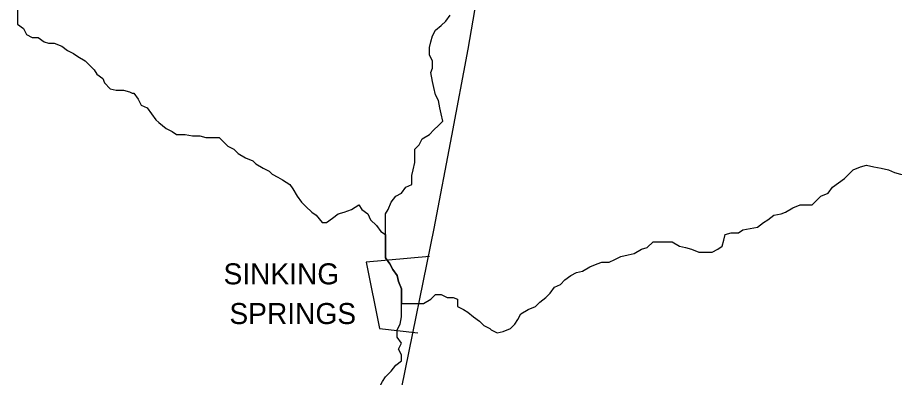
# Model space of a CAD drawing. Extents: x 0 to 40.2, y 0 to 22.
# Drawn here: x 4.306 to 5.119, y 17.878 to 18.212 of the extents above; entities that cross this region are included whole.
import ezdxf

# ---------------------------------------------------------------- set-up
doc = ezdxf.new("R2010")
doc.units = 0
doc.layers.add('Default', color=7, linetype='Continuous')

msp = doc.modelspace()

# ---------------------------------------------------------------- linework, layer by layer
at = {"layer": 'Default'}
for points in [[(4.7818, 18.51094), (4.75726, 18.37868), (4.73681, 18.26143), (4.72318, 18.18235), (4.70818, 18.10191), (4.69182, 18.01601), (4.66182, 17.86877)], [(4.31551, 18.30915), (4.31551, 18.30233), (4.31551, 18.29552), (4.31415, 18.29006), (4.31415, 18.28325), (4.31279, 18.27643), (4.31279, 18.26961), (4.31142, 18.26279), (4.31142, 18.25734), (4.31142, 18.25052), (4.3087, 18.24507), (4.3087, 18.23689), (4.3087, 18.23144), (4.30733, 18.22462), (4.30597, 18.2178), (4.30597, 18.21235), (4.30597, 18.20553), (4.30597, 18.20553)], [(4.64682, 18.01056), (4.64682, 18.01601), (4.64682, 18.02147), (4.64682, 18.02965), (4.64955, 18.03374), (4.65228, 18.04056), (4.65637, 18.04601), (4.66182, 18.04874), (4.66591, 18.05419), (4.67137, 18.05692), (4.67137, 18.0651), (4.67273, 18.07055), (4.67409, 18.07737), (4.67409, 18.08282), (4.67409, 18.08964), (4.67818, 18.09373), (4.68091, 18.09918), (4.68773, 18.10327), (4.69182, 18.10736), (4.69591, 18.11145), (4.7, 18.11554), (4.69863, 18.12236), (4.69727, 18.12782), (4.69591, 18.13463), (4.69318, 18.14009), (4.69182, 18.1469), (4.69045, 18.15236), (4.68909, 18.16054), (4.69045, 18.16463), (4.69045, 18.17144), (4.68773, 18.1769), (4.68773, 18.18372), (4.68909, 18.18917), (4.69045, 18.19462), (4.69318, 18.20008), (4.69863, 18.20417), (4.70272, 18.20826), (4.70681, 18.21371)], [(4.30597, 18.20553), (4.31142, 18.20144), (4.31415, 18.19599), (4.3196, 18.19326), (4.32506, 18.19326), (4.33051, 18.18917), (4.3346, 18.18781), (4.34005, 18.18781), (4.34687, 18.18508), (4.35233, 18.18099), (4.35778, 18.17826), (4.36187, 18.17554), (4.36869, 18.17144), (4.37141, 18.16872), (4.37687, 18.16326), (4.37959, 18.15917), (4.38505, 18.15508), (4.38641, 18.15099), (4.39186, 18.14554), (4.39732, 18.14418), (4.40414, 18.14418), (4.40959, 18.14281), (4.41232, 18.14145), (4.41368, 18.14145)], [(4.41368, 18.14145), (4.41777, 18.136), (4.4205, 18.13054), (4.42595, 18.12782), (4.43004, 18.12236), (4.43413, 18.11691), (4.43686, 18.11418), (4.44367, 18.10873), (4.44913, 18.106), (4.45322, 18.10327), (4.4614, 18.10327), (4.46822, 18.10191), (4.47503, 18.10191), (4.48049, 18.10055), (4.48594, 18.10055), (4.49276, 18.10055), (4.49685, 18.09646), (4.50094, 18.09237), (4.50639, 18.08964), (4.51048, 18.08555), (4.5173, 18.08146), (4.52412, 18.07873), (4.52684, 18.07601), (4.53366, 18.07192), (4.53911, 18.06919), (4.54048, 18.06782), (4.54184, 18.06646)], [(5.0354, 18.03783), (5.04222, 18.03783), (5.04631, 18.04192), (5.0504, 18.04601), (5.05721, 18.04874), (5.0613, 18.05419), (5.06676, 18.05828), (5.07221, 18.06237), (5.0763, 18.06646), (5.08039, 18.07055), (5.08721, 18.07328), (5.09266, 18.07464), (5.09948, 18.07328), (5.1063, 18.07192), (5.11311, 18.07055), (5.11857, 18.06782), (5.12402, 18.06646), (5.13084, 18.0651), (5.13766, 18.0651), (5.14447, 18.06237), (5.14856, 18.06101), (5.15538, 18.06101), (5.15538, 18.06101)], [(4.54184, 18.06646), (4.54729, 18.06373), (4.55138, 18.06101), (4.5582, 18.05692), (4.56093, 18.05283), (4.56502, 18.04601), (4.56911, 18.04056), (4.5732, 18.03647), (4.57865, 18.03101), (4.58274, 18.02829), (4.5882, 18.02147), (4.59229, 18.02147), (4.59774, 18.02556), (4.60319, 18.02965), (4.60865, 18.03101), (4.61547, 18.03374), (4.62228, 18.03783), (4.62501, 18.03374), (4.63046, 18.02965), (4.63319, 18.0242), (4.63864, 18.01874), (4.64273, 18.01329), (4.64682, 18.01056), (4.64682, 18.01056)], [(4.90042, 18.00374), (4.90724, 18.00374), (4.91269, 18.00374), (4.91951, 17.99965), (4.92496, 17.99829), (4.93042, 17.99693), (4.93723, 17.9942), (4.94269, 17.9942), (4.9495, 17.9942), (4.95496, 17.99693), (4.95905, 17.99965), (4.96041, 18.00511), (4.96177, 18.01056), (4.96723, 18.01192), (4.97404, 18.01192), (4.97814, 18.01465), (4.98495, 18.01601), (4.99177, 18.01738), (4.99722, 18.02147), (5.00131, 18.0242), (5.00677, 18.02829), (5.01358, 18.02965), (5.01767, 18.03101), (5.02449, 18.0351), (5.03131, 18.03783), (5.0354, 18.03783), (5.0354, 18.03783)], [(4.64682, 18.01056), (4.64682, 18.00783), (4.64682, 18.00102), (4.64682, 17.99556), (4.64682, 17.98875), (4.65091, 17.98329), (4.65364, 17.97784), (4.65773, 17.97239), (4.65909, 17.96693), (4.66182, 17.96011), (4.66182, 17.95466), (4.66182, 17.94648)], [(4.66182, 17.94648), (4.66182, 17.95466), (4.66182, 17.96011), (4.65909, 17.96693), (4.65773, 17.97239), (4.65364, 17.97784), (4.65091, 17.98329), (4.64682, 17.98875), (4.64682, 17.99556), (4.64682, 18.00102), (4.64682, 18.00783), (4.64682, 18.01056)], [(4.74499, 17.92194), (4.75044, 17.91921), (4.7559, 17.92058), (4.76271, 17.9233), (4.7668, 17.92739), (4.76953, 17.93148), (4.77226, 17.93694), (4.77908, 17.94103), (4.78589, 17.94375), (4.78998, 17.94784), (4.79544, 17.95193), (4.79953, 17.95602), (4.80362, 17.96148), (4.80907, 17.9642), (4.81316, 17.9683), (4.81861, 17.97239), (4.82407, 17.97511), (4.82952, 17.97648), (4.83634, 17.98057), (4.84316, 17.98329), (4.84725, 17.98466), (4.85406, 17.98466), (4.85952, 17.98738), (4.86497, 17.99011), (4.87179, 17.99147), (4.87724, 17.99284), (4.88406, 17.99693), (4.88951, 17.99829), (4.89497, 18.00374), (4.89906, 18.00374), (4.90042, 18.00374), (4.90042, 18.00374)], [(4.68773, 17.99011), (4.6291, 17.98466), (4.64137, 17.9233), (4.67682, 17.91921)], [(4.67818, 17.94648), (4.68227, 17.94648), (4.68909, 17.95057), (4.69318, 17.95466), (4.69863, 17.95466), (4.70409, 17.95193), (4.70954, 17.95193), (4.71363, 17.95057), (4.71363, 17.94375), (4.71909, 17.94103), (4.72318, 17.9383), (4.72863, 17.93421), (4.73408, 17.93012), (4.73817, 17.92603), (4.74363, 17.9233), (4.74363, 17.9233), (4.74499, 17.92194)], [(4.64137, 17.86331), (4.64137, 17.86877), (4.6441, 17.87422), (4.64682, 17.87831), (4.65228, 17.88376), (4.65637, 17.88922), (4.66182, 17.89331), (4.66182, 17.89876), (4.65909, 17.90421), (4.66182, 17.90967), (4.65773, 17.91512), (4.65773, 17.92194), (4.66046, 17.92739), (4.66182, 17.93421), (4.66182, 17.94239), (4.66182, 17.94648), (4.66182, 17.94648)], [(4.66182, 17.94648), (4.66728, 17.94648), (4.67409, 17.94648), (4.67818, 17.94648)]]:
    msp.add_lwpolyline(points, dxfattribs=at)

# ---------------------------------------------------------------- texts
for s, p in [('SINKING', (4.49685, 17.9642)), ('SPRINGS', (4.5023, 17.92739))]:
    msp.add_text(s, height=0.019502, dxfattribs=at).set_placement(p)

doc.saveas('drawing.dxf')
